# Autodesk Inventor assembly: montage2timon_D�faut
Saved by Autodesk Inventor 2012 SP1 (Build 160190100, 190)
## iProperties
Created: 2011-01
Part Number: montage2timon_D�faut
Document SubType Name: Assembly
Designer: eric
Mass: 224.141 g
Surface Area: 2423.2 cm^2
Volume: 224.141 cm^3
Density: 1 g/cm^3
Author: eric
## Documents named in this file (17)
- D:\Cours\Inventor salle SI\chariot_de_golf_2008\chariot_de_golf_trolem\montage2timon_Defaut.iam
- D:\Cours\Inventor salle SI\chariot_de_golf_2008\chariot_de_golf_trolem\31verrou_bas_Defaut.ipt
- D:\Cours\Inventor salle SI\chariot_de_golf_2008\chariot_de_golf_trolem\58embout_ovale_Defaut.ipt
- D:\Cours\Inventor salle SI\chariot_de_golf_2008\chariot_de_golf_trolem\bead60_Defaut.ipt
- D:\Cours\Inventor salle SI\chariot_de_golf_2008\chariot_de_golf_trolem\35Vis_CBLZ_M6_55.ipt
- D:\Cours\Inventor salle SI\chariot_de_golf_2008\chariot_de_golf_trolem\bead50_Defaut.ipt
- D:\Cours\Inventor salle SI\chariot_de_golf_2008\chariot_de_golf_trolem\bead51_Defaut.ipt
- D:\Cours\Inventor salle SI\chariot_de_golf_2008\chariot_de_golf_trolem\bead61_Defaut.ipt
- D:\Cours\Inventor salle SI\chariot_de_golf_2008\chariot_de_golf_trolem\bead52_Defaut.ipt
- D:\Cours\Inventor salle SI\chariot_de_golf_2008\chariot_de_golf_trolem\34support_avant_Defaut.ipt
- D:\Cours\Inventor salle SI\chariot_de_golf_2008\chariot_de_golf_trolem\2chappe_Defaut.ipt
- D:\Cours\Inventor salle SI\chariot_de_golf_2008\chariot_de_golf_trolem\2timon_Defaut.iam
- D:\Cours\Inventor salle SI\chariot_de_golf_2008\chariot_de_golf_trolem\bead53_Defaut.ipt
- D:\Cours\Inventor salle SI\chariot_de_golf_2008\chariot_de_golf_trolem\1carre_assemble_Defaut.iam
- D:\Cours\Inventor salle SI\chariot_de_golf_2008\chariot_de_golf_trolem\45bouchon_cylindrique_Defaut.ipt
- D:\Cours\Inventor salle SI\chariot_de_golf_2008\chariot_de_golf_trolem\53guide_cable_Defaut.ipt
- D:\Cours\Inventor salle SI\chariot_de_golf_2008\chariot_de_golf_trolem\36Ecrou H_ FR_ M6.ipt
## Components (16 placed, 16 different names)
1. 31verrou_bas_Defaut:1
2. 58embout_ovale_Defaut:1
3. bead60_Defaut:1
4. 35Vis_CBLZ_M6_55:1
5. bead50_Defaut:1
6. bead51_Defaut:1
7. bead61_Defaut:1
8. bead52_Defaut:1
9. 34support_avant_Defaut:1
10. 2chappe_Defaut:1
11. 2timon_Defaut:1 [sub-assembly]
12. bead53_Defaut:1
13. 1carre_assemble_Defaut:1 [sub-assembly]
14. 45bouchon_cylindrique_Defaut:1
15. 53guide_cable_Defaut:1
16. 36Ecrou H_ FR_ M6:1
